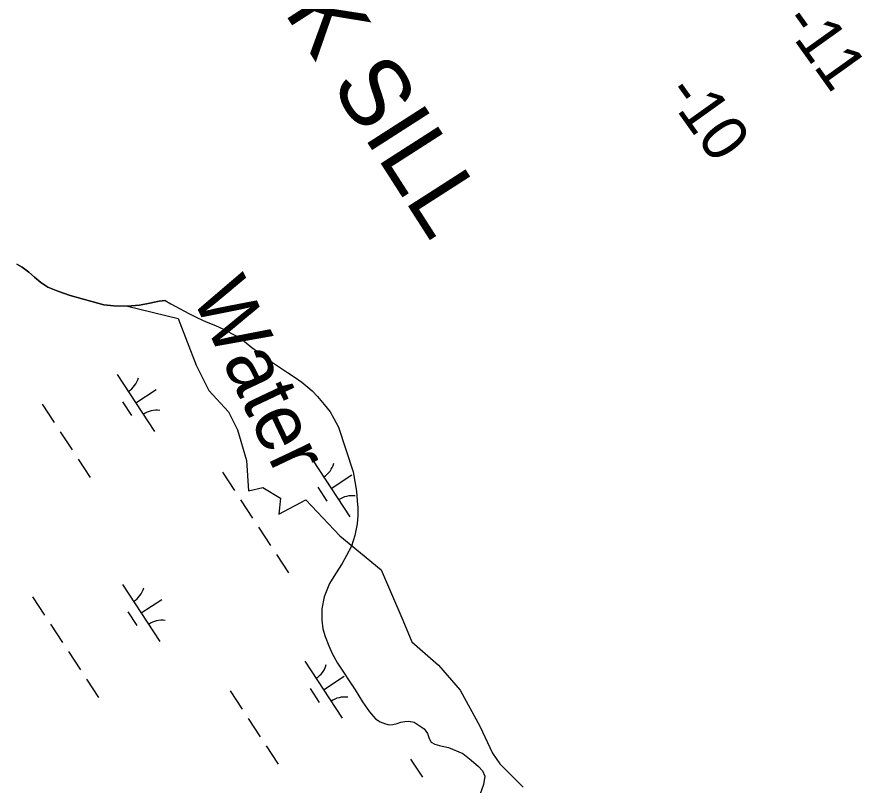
# Model space of a CAD drawing. Extents: x 3945642 to 3966284, y 206476 to 228921.
# Drawn here: x 3953528 to 3954147, y 219564 to 220127 of the extents above; entities that cross this region are included whole.
import ezdxf

# ---------------------------------------------------------------- set-up
doc = ezdxf.new("R2010")
doc.units = 0
for name, color, linetype in [('V-RIVR-EDGE', 7, 'Continuous'), ('V-RIVR-IDEN', 7, 'Continuous'), ('V-RIVR-RANG', 7, 'Continuous'), ('V-RRAP-SILL-IDEN', 7, 'Continuous'), ('V-TOPO-SHOR', 7, 'Continuous'), ('V-WETL-SWMP', 7, 'Continuous')]:
    doc.layers.add(name, color=color, linetype=linetype)

msp = doc.modelspace()

# ---------------------------------------------------------------- linework, layer by layer
at = {"layer": 'V-RIVR-EDGE'}
msp.add_lwpolyline([(3953608.69, 219914.87), (3953646, 219905.63), (3953659.14, 219871.46), (3953668.34, 219853.07), (3953682.8, 219837.3), (3953689.37, 219824.15), (3953695.94, 219801.81), (3953697.26, 219779.47), (3953707.77, 219782.1), (3953720.91, 219774.22), (3953719.6, 219762.39), (3953739.31, 219772.9), (3953764.28, 219746.62), (3953794.5, 219721.65), (3953810.27, 219684.85), (3953816.85, 219669.08), (3953836.56, 219652), (3953852.33, 219633.6), (3953866.78, 219607.32), (3953875.98, 219587.6), (3953881.24, 219579.72), (3953898.32, 219562.63)], dxfattribs=at)
at = {"layer": 'V-TOPO-SHOR'}
msp.add_lwpolyline([(3953636.46, 219918.94), (3953631.87, 219918.44), (3953625.03, 219916.89), (3953617.55, 219915.45), (3953608.69, 219914.87), (3953598.77, 219914.94), (3953591.52, 219915.74), (3953566.72, 219922.64), (3953557.89, 219925.69), (3953550.54, 219928.62), (3953545.45, 219932.18), (3953540.78, 219936.05), (3953536.54, 219939.6), (3953531.77, 219943.37), (3953527.73, 219945.53)], dxfattribs=at)
at = {"layer": 'V-WETL-SWMP'}
for p, q in [((3953527.73, 219945.53), (3953531.77, 219943.37)), ((3953531.77, 219943.37), (3953536.54, 219939.6)), ((3953536.54, 219939.6), (3953540.78, 219936.05)), ((3953540.78, 219936.05), (3953545.45, 219932.18)), ((3953545.45, 219932.18), (3953550.54, 219928.62)), ((3953550.54, 219928.62), (3953557.89, 219925.69)), ((3953557.89, 219925.69), (3953566.72, 219922.64)), ((3953566.72, 219922.64), (3953591.52, 219915.74)), ((3953617.55, 219915.45), (3953625.03, 219916.89)), ((3953625.03, 219916.89), (3953631.87, 219918.44)), ((3953631.87, 219918.44), (3953636.46, 219918.94)), ((3953636.46, 219918.94), (3953640.48, 219916.53)), ((3953591.52, 219915.74), (3953598.77, 219914.94)), ((3953598.77, 219914.94), (3953608.69, 219914.87)), ((3953608.69, 219914.87), (3953617.55, 219915.45)), ((3953640.48, 219916.53), (3953647.37, 219912.81)), ((3953647.37, 219912.81), (3953653.69, 219909.38)), ((3953653.69, 219909.38), (3953660.15, 219906.23)), ((3953660.15, 219906.23), (3953666.4, 219903.38)), ((3953666.4, 219903.38), (3953673.22, 219900.59)), ((3953673.22, 219900.59), (3953679.47, 219897.59)), ((3953679.47, 219897.59), (3953685.43, 219894.6)), ((3953685.43, 219894.6), (3953691.6, 219891.24)), ((3953691.6, 219891.24), (3953699.77, 219884.55)), ((3953699.77, 219884.55), (3953704.93, 219880.77)), ((3953704.93, 219880.77), (3953709.66, 219877.06)), ((3953709.66, 219877.06), (3953714.83, 219873.49)), ((3953714.83, 219873.49), (3953720.71, 219869.63)), ((3953720.71, 219869.63), (3953725.94, 219866.13)), ((3953601.11, 219864.8), (3953628.51, 219822.97)), ((3953725.94, 219866.13), (3953730.82, 219863.14)), ((3953730.82, 219863.14), (3953736.41, 219859.14)), ((3953736.41, 219859.14), (3953740.78, 219855.58)), ((3953740.78, 219855.58), (3953743.94, 219852.75)), ((3953614.81, 219843.88), (3953629.86, 219853.75)), ((3953743.94, 219852.75), (3953747.8, 219848.61)), ((3953546.41, 219842.96), (3953555.18, 219829.57)), ((3953605.06, 219844.67), (3953611.64, 219834.64)), ((3953747.8, 219848.61), (3953752.87, 219842.67)), ((3953752.87, 219842.67), (3953757.08, 219837.38)), ((3953757.08, 219837.38), (3953759.93, 219832.53)), ((3953759.93, 219832.53), (3953763.2, 219826.23)), ((3953763.2, 219826.23), (3953773.92, 219793.44)), ((3953559.57, 219822.88), (3953568.33, 219809.5)), ((3953572.72, 219802.81), (3953581.48, 219789.42)), ((3953744.18, 219802.25), (3953771.58, 219760.43)), ((3953678.39, 219793.13), (3953687.15, 219779.75)), ((3953773.92, 219793.44), (3953775.24, 219786.52)), ((3953757.88, 219781.34), (3953772.94, 219791.21)), ((3953748.14, 219782.13), (3953754.71, 219772.1)), ((3953775.24, 219786.52), (3953776.34, 219779.3)), ((3953776.34, 219779.3), (3953776.8, 219772.31)), ((3953691.54, 219773.05), (3953700.3, 219759.67)), ((3953776.8, 219772.31), (3953777.34, 219767.04)), ((3953777.34, 219767.04), (3953777.3, 219761.42)), ((3953777.3, 219761.42), (3953776.97, 219755.3)), ((3953704.69, 219752.98), (3953713.46, 219739.59)), ((3953776.97, 219755.3), (3953775.1, 219746.95)), ((3953775.1, 219746.95), (3953772.67, 219738.97)), ((3953772.67, 219738.97), (3953769.16, 219732.22)), ((3953717.84, 219732.9), (3953726.61, 219719.52)), ((3953769.16, 219732.22), (3953765.88, 219726.41)), ((3953765.88, 219726.41), (3953761, 219718.88)), ((3953761, 219718.88), (3953756.77, 219711.63)), ((3953605.04, 219711.1), (3953632.44, 219669.28)), ((3953756.77, 219711.63), (3953752.88, 219701.93)), ((3953539.25, 219701.98), (3953548.01, 219688.59)), ((3953752.88, 219701.93), (3953751.16, 219693.3)), ((3953618.74, 219690.19), (3953633.8, 219700.05)), ((3953609, 219690.98), (3953615.57, 219680.94)), ((3953751.16, 219693.3), (3953750.96, 219684.79)), ((3953552.4, 219681.9), (3953561.17, 219668.52)), ((3953750.96, 219684.79), (3953751.7, 219678.59)), ((3953751.7, 219678.59), (3953753.46, 219672.82)), ((3953753.46, 219672.82), (3953756.23, 219666.02)), ((3953756.23, 219666.02), (3953758.71, 219660.46)), ((3953565.55, 219661.83), (3953574.32, 219648.44)), ((3953758.71, 219660.46), (3953762.62, 219653.51)), ((3953738.63, 219654.88), (3953766.03, 219613.05)), ((3953762.62, 219653.51), (3953775.45, 219633.96)), ((3953578.7, 219641.75), (3953587.47, 219628.37)), ((3953752.33, 219633.96), (3953767.38, 219643.83)), ((3953683.93, 219633.04), (3953692.7, 219619.66)), ((3953742.58, 219634.76), (3953749.16, 219624.72)), ((3953775.45, 219633.96), (3953780.79, 219625.06)), ((3953780.79, 219625.06), (3953786, 219617.74)), ((3953786, 219617.74), (3953790.36, 219612.74)), ((3953697.09, 219612.96), (3953705.85, 219599.58)), ((3953790.36, 219612.74), (3953793.81, 219610.48)), ((3953793.81, 219610.48), (3953797.62, 219608.87)), ((3953797.62, 219608.87), (3953800.42, 219608.35)), ((3953800.42, 219608.35), (3953803.09, 219608.62)), ((3953803.09, 219608.62), (3953806.19, 219609.31)), ((3953806.19, 219609.31), (3953808.79, 219610.09)), ((3953808.79, 219610.09), (3953811.9, 219610.79)), ((3953811.9, 219610.79), (3953814.71, 219610.84)), ((3953814.71, 219610.84), (3953818.74, 219610.09)), ((3953818.74, 219610.09), (3953825.91, 219605.35)), ((3953825.91, 219605.35), (3953828.33, 219601.88)), ((3953828.33, 219601.88), (3953829.61, 219598.19)), ((3953829.61, 219598.19), (3953831.1, 219595.52)), ((3953831.1, 219595.52), (3953833.76, 219594.13)), ((3953710.24, 219592.89), (3953719.01, 219579.5)), ((3953833.76, 219594.13), (3953837.28, 219593.24)), ((3953837.28, 219593.24), (3953840.3, 219592.5)), ((3953840.3, 219592.5), (3953843.75, 219591.68)), ((3953843.75, 219591.68), (3953854.25, 219587.28)), ((3953815.91, 219583.21), (3953824.67, 219569.83)), ((3953854.25, 219587.28), (3953860.26, 219582.48)), ((3953860.26, 219582.48), (3953865.71, 219577.83)), ((3953865.71, 219577.83), (3953868.78, 219574.64)), ((3953868.78, 219574.64), (3953870.48, 219570.59)), ((3953870.48, 219570.59), (3953869.43, 219564.55)), ((3953869.43, 219564.55), (3953866.71, 219557))]:
    msp.add_line(p, q, dxfattribs=at)
for centre, start, end in [((3953599.87, 219867.12), 302.45745, 344.00111), ((3953630.14, 219820.91), 82.45745, 124.00111), ((3953742.94, 219804.58), 302.45745, 344.00111), ((3953773.21, 219758.37), 82.45745, 124.00111), ((3953603.8, 219713.43), 302.45745, 344.00111), ((3953634.07, 219667.22), 82.45745, 124.00111), ((3953737.39, 219657.2), 302.45745, 344.00111), ((3953767.66, 219610.99), 82.45745, 124.00111)]:
    msp.add_arc(centre, 17.62, start, end, dxfattribs=at)

# ---------------------------------------------------------------- texts
at = {"layer": 'V-RIVR-IDEN'}
msp.add_text('Water', height=42, rotation=295.35391, dxfattribs=at).set_placement((3953655.22, 219922.76))
at = {"layer": 'V-RIVR-RANG'}
for s, p in [('-11', (3954087.3, 220122.73)), ('-10', (3954001.64, 220070.61))]:
    msp.add_text(s, height=33.5, rotation=305.54339, dxfattribs=at).set_placement(p)
at = {"layer": 'V-RRAP-SILL-IDEN'}
msp.add_text('ROCK SILL', height=50, rotation=302.67566, dxfattribs=at).set_placement((3953642.74, 220255.25))

doc.saveas('drawing.dxf')
